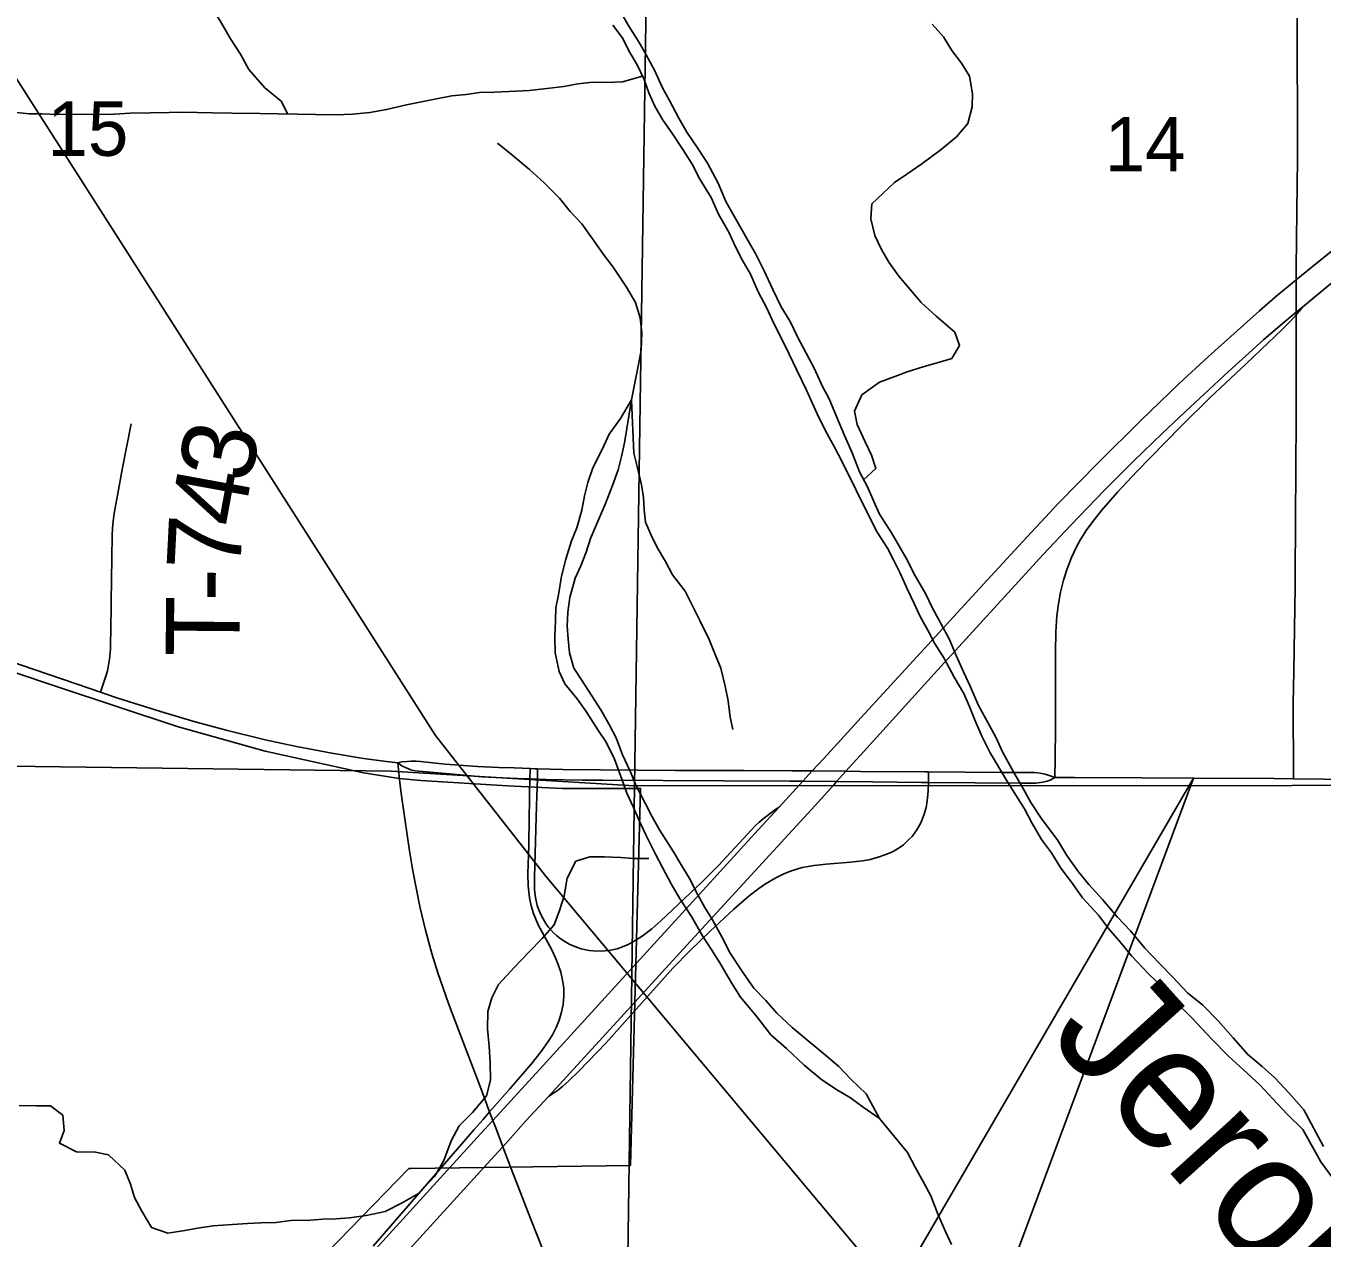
# Model space of a CAD drawing. Extents: x 0 to 34, y 0 to 22.
# Drawn here: x 16.641 to 17.64, y 16.839 to 17.772 of the extents above; entities that cross this region are included whole.
import ezdxf

# ---------------------------------------------------------------- set-up
doc = ezdxf.new("R2010")
doc.units = 0
for name, color, linetype in [('GM_X_Corporation', 7, 'Continuous'), ('GM_X_County_Road', 7, 'Continuous'), ('GM_X_Interchange_Ramps', 7, 'Continuous'), ('GM_X_Interstate_Route', 7, 'Continuous'), ('GM_X_Major_River', 7, 'Continuous'), ('GM_X_Major_River_Text', 7, 'Continuous'), ('GM_X_Minor_River', 7, 'Continuous'), ('GM_X_Rail_Line', 7, 'Continuous'), ('GM_X_Section', 7, 'Continuous'), ('GM_X_Section_Text', 7, 'Continuous'), ('GM_X_Township_Road', 7, 'Continuous'), ('GM_X_Township_Road_Text', 7, 'Continuous'), ('GM_X_US_Location', 7, 'Continuous'), ('GM_X_US_Route', 7, 'Continuous'), ('SH_Text', 7, 'Continuous')]:
    doc.layers.add(name, color=color, linetype=linetype)

msp = doc.modelspace()

# ---------------------------------------------------------------- linework, layer by layer
at = {"layer": 'GM_X_Corporation'}
msp.add_lwpolyline([(16.75517, 16.70645), (16.9364, 16.89274), (16.93792, 16.89273), (17.10691, 16.89509), (17.11474, 17.18529), (17.05464, 17.18529), (17.01229, 17.18726), (16.94547, 17.19147), (16.92893, 17.19284), (16.90141, 17.19739), (16.82566, 17.21406), (16.75792, 17.23304), (16.66586, 17.26338), (16.59752, 17.2862)], dxfattribs=at)
at = {"layer": 'GM_X_County_Road'}
msp.add_line((16.92915, 17.19217), (16.92782, 17.20492), dxfattribs=at)
for points in [[(17.01533, 16.89187), (17.00867, 16.90946), (17.00322, 16.92386), (17.00102, 16.92969), (16.99853, 16.93626), (16.99112, 16.95584), (16.97449, 16.99937), (16.96674, 17.01972), (16.95864, 17.04326), (16.95398, 17.05812), (16.94904, 17.07615), (16.94482, 17.09435), (16.93933, 17.12182), (16.93675, 17.13717), (16.93328, 17.16181), (16.93007, 17.18335), (16.92915, 17.19217)], [(17.04034, 16.8282), (17.02995, 16.85419), (17.01533, 16.89187)]]:
    msp.add_lwpolyline(points, dxfattribs=at)
at = {"layer": 'GM_X_Interchange_Ramps'}
for points in [[(17.43379, 17.19368), (17.43396, 17.20766), (17.43409, 17.21467), (17.4343, 17.22523), (17.43422, 17.29026), (17.43451, 17.30573), (17.43537, 17.31809), (17.43652, 17.32731), (17.43819, 17.33644), (17.44041, 17.34546), (17.4432, 17.35432), (17.44655, 17.36298), (17.45055, 17.37136), (17.45353, 17.37677), (17.45849, 17.38462), (17.46398, 17.39209), (17.46981, 17.39932), (17.48214, 17.41324), (17.4969, 17.42912), (17.51848, 17.45133), (17.53187, 17.46481), (17.55321, 17.48583), (17.5814, 17.51234), (17.59797, 17.52822), (17.60879, 17.53864), (17.6149, 17.54481), (17.61957, 17.54995), (17.62449, 17.55585)], [(17.02976, 17.20054), (17.02974, 17.19952), (17.02958, 17.19256), (17.02934, 17.18196), (17.02921, 17.17578), (17.02895, 17.16326), (17.02874, 17.14146), (17.02806, 17.1196), (17.02824, 17.11023), (17.02922, 17.10092), (17.03054, 17.09486), (17.03233, 17.08891), (17.03599, 17.08032), (17.04631, 17.06101), (17.04904, 17.0554), (17.05142, 17.0496), (17.05335, 17.04368), (17.05475, 17.03761), (17.05555, 17.03143), (17.05567, 17.02521), (17.05512, 17.01901), (17.05392, 17.01289), (17.05209, 17.00695), (17.04973, 17.00118), (17.04685, 16.99565), (17.04363, 16.99031), (17.03824, 16.98263), (17.03042, 16.97288), (17.01401, 16.95403), (16.99853, 16.93626), (16.99351, 16.9305), (16.98667, 16.92263), (16.9772, 16.91174), (16.90875, 16.83294)], [(17.22144, 17.17087), (17.219, 17.16926), (17.21444, 17.16607), (17.20913, 17.16192), (17.2061, 17.15936), (17.2031, 17.15641), (17.17507, 17.12615), (17.16186, 17.11308), (17.13034, 17.08326), (17.12333, 17.07714), (17.11593, 17.07151), (17.11072, 17.06816), (17.10526, 17.06519), (17.09955, 17.06278), (17.09661, 17.06185), (17.09058, 17.06049), (17.08441, 17.05996), (17.07822, 17.06017), (17.07515, 17.06056), (17.06909, 17.06189), (17.06613, 17.06283), (17.06041, 17.06523), (17.05767, 17.06667), (17.05503, 17.0683), (17.0525, 17.07009), (17.05009, 17.07204), (17.04782, 17.07414), (17.04567, 17.07638), (17.04368, 17.07875), (17.04183, 17.08124), (17.03863, 17.08655), (17.03617, 17.09221), (17.03518, 17.09515), (17.03387, 17.10118), (17.0332, 17.10732), (17.03299, 17.11663), (17.03444, 17.16312), (17.03492, 17.17966), (17.03527, 17.19239), (17.03546, 17.19947), (17.03548, 17.20036)], [(17.29344, 17.13111), (17.29777, 17.13223), (17.30365, 17.13427), (17.30931, 17.13682), (17.31465, 17.14003), (17.31715, 17.14184), (17.32172, 17.14607), (17.32381, 17.14834), (17.3275, 17.15334), (17.33054, 17.15878), (17.33292, 17.16455), (17.33467, 17.17052), (17.33532, 17.17356), (17.33608, 17.18029), (17.33629, 17.18362), (17.33639, 17.18985)], [(17.33639, 17.18985), (17.33652, 17.19698), (17.33654, 17.19812)], [(17.04382, 16.94812), (17.05068, 16.95275), (17.05456, 16.95588), (17.05939, 16.96021), (17.06741, 16.96776), (17.08801, 16.9891), (17.13962, 17.04684), (17.15264, 17.06024), (17.16833, 17.07537), (17.18666, 17.09224), (17.19844, 17.10245), (17.20583, 17.10818), (17.21093, 17.11174), (17.21896, 17.11651), (17.22455, 17.11924), (17.23029, 17.12162), (17.23921, 17.12432), (17.24836, 17.12605), (17.25765, 17.12702), (17.27632, 17.12838), (17.28561, 17.12953), (17.29171, 17.13067), (17.29344, 17.13111)]]:
    msp.add_lwpolyline(points, dxfattribs=at)
at = {"layer": 'GM_X_Interstate_Route'}
for points in [[(17.60938, 17.56843), (17.61965, 17.57682), (17.63187, 17.5868), (17.68505, 17.62973)], [(17.22144, 17.17087), (17.23972, 17.19072), (17.24703, 17.19868), (17.2558, 17.2082), (17.28722, 17.24264), (17.34186, 17.30214), (17.37545, 17.33881), (17.40908, 17.37543), (17.43667, 17.40489), (17.46704, 17.43599), (17.50015, 17.46876), (17.52932, 17.49667), (17.55206, 17.51779), (17.59133, 17.55305), (17.60542, 17.5652), (17.60938, 17.56843)], [(17.62449, 17.55585), (17.64901, 17.57602)], [(17.26373, 17.18829), (17.26573, 17.19049), (17.27291, 17.19843), (17.28668, 17.21362), (17.34098, 17.27347), (17.42481, 17.36529), (17.44605, 17.38802), (17.47201, 17.41484), (17.494, 17.43685), (17.51641, 17.45843), (17.52999, 17.47122), (17.53437, 17.47533), (17.5487, 17.48876), (17.56762, 17.5062), (17.5805, 17.51806), (17.59453, 17.53065), (17.60736, 17.54169), (17.61957, 17.5518), (17.62449, 17.55585)], [(17.11026, 17.0206), (17.14193, 17.0554), (17.18815, 17.10578), (17.24912, 17.17216), (17.26373, 17.18829)], [(16.89292, 16.81105), (16.99155, 16.91933), (17.00102, 16.92969), (17.03976, 16.97208), (17.09003, 17.02719), (17.16556, 17.1097), (17.20532, 17.15335), (17.22144, 17.17087)], [(16.99408, 16.89332), (16.99949, 16.89925), (17.00867, 16.90946), (17.0265, 16.9293), (17.04382, 16.94812), (17.10217, 17.01172), (17.11026, 17.0206)], [(16.93454, 16.82811), (16.99408, 16.89332)]]:
    msp.add_lwpolyline(points, dxfattribs=at)
at = {"layer": 'GM_X_Major_River'}
for points in [[(17.40256, 17.19694), (17.39351, 17.21333), (17.38824, 17.22475), (17.38069, 17.23884), (17.37503, 17.24913), (17.36863, 17.26397), (17.36336, 17.27502), (17.35771, 17.28758), (17.35244, 17.30053), (17.33924, 17.32452), (17.33434, 17.3348), (17.32528, 17.3508), (17.32039, 17.36071), (17.31435, 17.37099), (17.30793, 17.38204), (17.29887, 17.39652), (17.29435, 17.40604), (17.28946, 17.41746), (17.28342, 17.42889), (17.27778, 17.44373), (17.27175, 17.45706), (17.26573, 17.47153), (17.26008, 17.48523), (17.2548, 17.49476), (17.2484, 17.50884), (17.24237, 17.52027), (17.23558, 17.53284), (17.22993, 17.54465), (17.22313, 17.55608), (17.21673, 17.5694), (17.20957, 17.58426), (17.20353, 17.59644), (17.1975, 17.60673), (17.18693, 17.62578), (17.18052, 17.6372), (17.1745, 17.65129), (17.1662, 17.66653), (17.15903, 17.67758), (17.15034, 17.69054), (17.1443, 17.7012), (17.13714, 17.71492), (17.13148, 17.7252), (17.12583, 17.73777), (17.11904, 17.74996), (17.11376, 17.75948), (17.10583, 17.77205), (17.09942, 17.78348)], [(17.09331, 17.77287), (17.10049, 17.76334), (17.10652, 17.75191), (17.11218, 17.74239), (17.11746, 17.73096), (17.12121, 17.72069), (17.12573, 17.71041), (17.13177, 17.70012), (17.13932, 17.68907), (17.14726, 17.67725), (17.15443, 17.66582), (17.16046, 17.65439), (17.16914, 17.6403), (17.17479, 17.62735), (17.18309, 17.61287), (17.18761, 17.60259), (17.19289, 17.59231), (17.1993, 17.58126), (17.20533, 17.56755), (17.21212, 17.55499), (17.21739, 17.54318), (17.22456, 17.52909), (17.22908, 17.51957), (17.23511, 17.50738), (17.24264, 17.49177), (17.25168, 17.47121), (17.25847, 17.45826), (17.26413, 17.44798), (17.26978, 17.43731), (17.29165, 17.39314), (17.29692, 17.38247), (17.30485, 17.37028), (17.30975, 17.36076), (17.31465, 17.35085), (17.3203, 17.33829), (17.32558, 17.32762), (17.3301, 17.31772), (17.33614, 17.30668), (17.34104, 17.29716), (17.34821, 17.28572), (17.35613, 17.27087), (17.36368, 17.2583), (17.36782, 17.24878), (17.37196, 17.2385), (17.37761, 17.22555), (17.38401, 17.21261)], [(17.38401, 17.21261), (17.39647, 17.19165), (17.40251, 17.18213), (17.41044, 17.16955), (17.41609, 17.15889), (17.42364, 17.14593), (17.4312, 17.13564), (17.43837, 17.12383), (17.44744, 17.11201), (17.45499, 17.10095), (17.46747, 17.0876), (17.47503, 17.0773), (17.48486, 17.06624), (17.4928, 17.05633), (17.50603, 17.04259), (17.51739, 17.03152), (17.5257, 17.02198), (17.53932, 17.00862), (17.55445, 16.99259), (17.56769, 16.97885), (17.57904, 16.96855), (17.59153, 16.95709), (17.60174, 16.9464), (17.61271, 16.93458), (17.62482, 16.92274)], [(17.62563, 16.93794), (17.61391, 16.95091), (17.60332, 16.96236), (17.59348, 16.97114), (17.5825, 16.98031), (17.57116, 16.99328), (17.55944, 17.00625), (17.54771, 17.01846), (17.53598, 17.02801), (17.52463, 17.03984), (17.51442, 17.05053), (17.50307, 17.06236), (17.49211, 17.07571), (17.48189, 17.08639), (17.47055, 17.09974), (17.45996, 17.11119), (17.45203, 17.12111), (17.44296, 17.13369), (17.43617, 17.14512), (17.42332, 17.16227), (17.41539, 17.17447), (17.40822, 17.18742), (17.40256, 17.19694)], [(17.64056, 16.90963), (17.62563, 16.93794)], [(17.62482, 16.92274), (17.6386, 16.89787), (17.64701, 16.88629)]]:
    msp.add_lwpolyline(points, dxfattribs=at)
at = {"layer": 'GM_X_Minor_River'}
for points in [[(16.84324, 17.70445), (16.83796, 17.71435), (16.82547, 17.72467), (16.81299, 17.73878), (16.80658, 17.75059), (16.79903, 17.7624), (16.79111, 17.77612), (16.78242, 17.78946), (16.77222, 17.80242), (16.76543, 17.81386), (16.75563, 17.83442), (16.75035, 17.84546), (16.74621, 17.85498)], [(17.28656, 17.42294), (17.29596, 17.43149), (17.29258, 17.44177), (17.28768, 17.45205), (17.28165, 17.46538), (17.27941, 17.47565), (17.28515, 17.48816), (17.29885, 17.49798), (17.31064, 17.50249), (17.32014, 17.50586), (17.33307, 17.50999), (17.34485, 17.51335), (17.35435, 17.51635), (17.36046, 17.5262), (17.3567, 17.53648), (17.34232, 17.5487), (17.33097, 17.55939), (17.32227, 17.56931), (17.31357, 17.57961), (17.30602, 17.59028), (17.30036, 17.60019), (17.29508, 17.61085), (17.29209, 17.62379), (17.29289, 17.63518), (17.31042, 17.65182), (17.31993, 17.65824), (17.33135, 17.66617), (17.3462, 17.67712), (17.358, 17.68695), (17.36677, 17.69717), (17.37023, 17.71008), (17.37027, 17.71995), (17.36804, 17.73364), (17.362, 17.74355), (17.35444, 17.75346), (17.34803, 17.76375), (17.33933, 17.77367)], [(17.11622, 17.73363), (17.10074, 17.72914), (17.08897, 17.72881), (17.07796, 17.72886), (17.06657, 17.72777), (17.05555, 17.72554), (17.04264, 17.72408), (17.02896, 17.72262), (17.01871, 17.72191), (17.00238, 17.72122), (16.99061, 17.72089), (16.98036, 17.71942), (16.96934, 17.71833), (16.95756, 17.7161), (16.94617, 17.71387), (16.93439, 17.71164), (16.91919, 17.70791), (16.90627, 17.70569), (16.89298, 17.70423), (16.88045, 17.7039), (16.8645, 17.70397), (16.85046, 17.70442), (16.83565, 17.70448), (16.8216, 17.70493), (16.79996, 17.70502), (16.78516, 17.70547), (16.77339, 17.70552), (16.76276, 17.70595), (16.75175, 17.70562), (16.73732, 17.7053), (16.72175, 17.70499), (16.7096, 17.70429), (16.69555, 17.70397), (16.68379, 17.7044), (16.66594, 17.7041), (16.65379, 17.70454), (16.64392, 17.70458), (16.63216, 17.70577)], [(17.10784, 17.48439), (17.11093, 17.49996), (17.11325, 17.51173), (17.11519, 17.52274), (17.11562, 17.53604), (17.11452, 17.54744), (17.11076, 17.55924), (17.10397, 17.57105), (17.09378, 17.58667), (17.08622, 17.59621), (17.07904, 17.6065), (17.0696, 17.61984), (17.06052, 17.62938), (17.05221, 17.63968), (17.04048, 17.65151), (17.02912, 17.66182), (17.01663, 17.67214), (17.00452, 17.68207)], [(17.10784, 17.48439), (17.09943, 17.46999), (17.09066, 17.45787), (17.0853, 17.44612), (17.07804, 17.43209), (17.0742, 17.42071), (17.07151, 17.41046), (17.06957, 17.39945), (17.06572, 17.38579), (17.06151, 17.37592), (17.05728, 17.36188), (17.05382, 17.3486), (17.05149, 17.33417), (17.04956, 17.3243), (17.04914, 17.31442), (17.04872, 17.30188), (17.04905, 17.28972), (17.05204, 17.27527), (17.05656, 17.26575), (17.06601, 17.25431), (17.07281, 17.2444), (17.08187, 17.2303), (17.08829, 17.22077), (17.0947, 17.20782), (17.09921, 17.19526), (17.1041, 17.18156), (17.10937, 17.17052), (17.11351, 17.161), (17.11879, 17.14958), (17.12633, 17.13472), (17.13161, 17.12444), (17.13839, 17.11187), (17.14481, 17.10082), (17.15387, 17.08672), (17.16255, 17.07186), (17.16972, 17.06081), (17.17576, 17.0509), (17.18482, 17.03566), (17.19161, 17.02462), (17.20371, 17.01012), (17.21505, 16.99563), (17.22716, 16.98494), (17.24078, 16.97234), (17.25441, 16.96088), (17.26653, 16.95284), (17.27638, 16.9471), (17.28622, 16.93983), (17.29872, 16.93104)], [(17.10784, 17.48439), (17.1024, 17.45136), (17.10009, 17.44073), (17.09739, 17.43048), (17.09318, 17.41834), (17.08781, 17.40469), (17.08168, 17.39027), (17.07632, 17.37776), (17.07287, 17.36713), (17.06865, 17.35651), (17.06444, 17.34703), (17.06021, 17.33223), (17.05866, 17.32084), (17.05824, 17.3102), (17.05896, 17.30032), (17.06006, 17.28967), (17.06344, 17.27788), (17.06986, 17.26797), (17.07665, 17.2573), (17.08421, 17.24587), (17.09062, 17.23444), (17.0959, 17.22415), (17.10078, 17.21121), (17.10682, 17.19865), (17.11133, 17.18723), (17.1185, 17.17352), (17.12339, 17.16399), (17.12943, 17.15333), (17.14, 17.13656), (17.14566, 17.12704), (17.15246, 17.11599), (17.15887, 17.10342), (17.16415, 17.09351), (17.17018, 17.08399), (17.17735, 17.07104), (17.18376, 17.05847), (17.1932, 17.04399), (17.20189, 17.03141), (17.21135, 17.02187), (17.21967, 17.01233), (17.23139, 17.00126), (17.24389, 16.99094), (17.25714, 16.97986), (17.26735, 16.97108), (17.27681, 16.96154), (17.28854, 16.95008), (17.29872, 16.93104)], [(17.10784, 17.48439), (17.10959, 17.44335), (17.11221, 17.43308), (17.11558, 17.419), (17.11706, 17.40911), (17.11741, 17.39961), (17.11851, 17.39011), (17.12303, 17.38021), (17.12755, 17.37069), (17.13397, 17.36002), (17.13925, 17.34974), (17.14907, 17.33715), (17.15435, 17.32687), (17.16076, 17.31392), (17.16754, 17.29983), (17.17168, 17.28955), (17.17658, 17.27775), (17.17994, 17.26406), (17.18218, 17.25265), (17.18365, 17.2401), (17.1859, 17.23059)], [(16.63633, 16.94106), (16.64963, 16.94101), (16.66027, 16.94097), (16.66974, 16.93372), (16.67085, 16.92193), (16.6674, 16.91206), (16.6803, 16.90556), (16.69511, 16.90513), (16.70498, 16.90319), (16.71749, 16.89137), (16.72201, 16.88071), (16.72502, 16.87044), (16.73069, 16.85978), (16.73825, 16.84721), (16.75078, 16.84299), (16.7637, 16.84484), (16.77358, 16.84671), (16.78574, 16.84856), (16.80056, 16.84965), (16.81196, 16.85037), (16.82221, 16.85072), (16.83399, 16.85105), (16.84539, 16.85254), (16.86059, 16.85286), (16.87009, 16.85359), (16.87996, 16.85393), (16.8906, 16.85466), (16.90353, 16.85651), (16.91797, 16.8595), (16.93128, 16.8663), (16.94384, 16.87347), (16.95642, 16.88673), (16.96329, 16.89886), (16.96903, 16.91405), (16.97514, 16.92542), (16.98543, 16.93565), (16.9961, 16.94853), (16.99918, 16.96068), (16.99883, 16.97398), (16.99811, 16.98691), (16.99701, 17.00021), (16.99705, 17.01351), (17.00012, 17.02415), (17.00546, 17.03439), (17.01766, 17.04765), (17.02909, 17.05939), (17.039, 17.06961), (17.04814, 17.08022), (17.05235, 17.09122), (17.05581, 17.10261), (17.05812, 17.11629), (17.065, 17.12919), (17.07565, 17.13257), (17.08704, 17.13253), (17.09958, 17.1321), (17.10907, 17.13131), (17.12123, 17.13127)], [(17.29872, 16.93104), (17.32027, 16.9051), (17.3263, 16.89368), (17.33271, 16.88225), (17.33837, 16.87158), (17.34402, 16.85712), (17.34928, 16.84456), (17.35418, 16.83427)]]:
    msp.add_lwpolyline(points, dxfattribs=at)
at = {"layer": 'GM_X_Rail_Line'}
msp.add_lwpolyline([(17.91677, 16.34), (17.62614, 16.49085), (17.58753, 16.51429), (17.54723, 16.53981), (17.50751, 16.57084), (17.47262, 16.60675), (17.41087, 16.67499), (17.34012, 16.75867), (17.28737, 16.82433), (17.04167, 17.11786), (16.95677, 17.22601), (16.87058, 17.36118), (16.63389, 17.73196), (16.39363, 18.10985), (16.36893, 18.14437), (16.34317, 18.17612), (16.30708, 18.2084), (16.27461, 18.2294), (16.21709, 18.26238), (16.14636, 18.29525), (15.65156, 18.4846)], dxfattribs=at)
at = {"layer": 'GM_X_Section'}
for points in [[(17.12534, 18.20792), (17.11005, 17.18727), (16.92281, 17.19862), (16.09999, 17.2094), (16.11682, 18.21604)], [(17.12534, 18.20792), (18.12874, 18.1928), (18.12281, 17.18769), (17.11005, 17.18727)], [(16.09999, 17.2094), (16.92281, 17.19862), (17.11005, 17.18727), (17.09585, 16.18898), (16.08772, 16.1952)], [(18.12281, 17.18769), (18.11686, 16.1822), (17.09585, 16.18898), (17.11005, 17.18727)]]:
    msp.add_lwpolyline(points, close=True, dxfattribs=at)
at = {"layer": 'GM_X_Township_Road'}
for points in [[(17.61764, 17.19263), (17.61754, 17.21751), (17.61727, 17.22894), (17.61736, 17.25066), (17.61778, 17.27548), (17.61877, 17.34067), (17.61913, 17.39967), (17.61937, 17.42449), (17.61956, 17.47723), (17.61958, 17.52998), (17.61957, 17.54995), (17.61957, 17.5518), (17.61957, 17.55792), (17.61965, 17.57682), (17.61969, 17.58586), (17.62022, 17.62931), (17.62068, 17.66966), (17.62058, 17.71312), (17.62047, 17.74106), (17.62047, 17.7783)], [(16.69886, 17.25926), (16.70265, 17.27079), (16.70421, 17.27582), (16.70512, 17.28011), (16.70586, 17.28489), (16.70652, 17.2925), (16.70663, 17.29879), (16.70672, 17.30526), (16.70717, 17.32854), (16.70744, 17.34643), (16.70762, 17.36235), (16.7079, 17.38024), (16.70798, 17.38545), (16.70852, 17.39094), (16.70907, 17.39507), (16.70979, 17.39993), (16.71212, 17.41219), (16.71566, 17.4307), (16.71888, 17.44759), (16.72237, 17.46591)]]:
    msp.add_lwpolyline(points, dxfattribs=at)
at = {"layer": 'GM_X_US_Route'}
for points in [[(16.26836, 17.41004), (16.38063, 17.36959), (16.41632, 17.35658), (16.42569, 17.35329), (16.46664, 17.33891), (16.53416, 17.31521), (16.55077, 17.30937), (16.56256, 17.30521), (16.5863, 17.29736), (16.60076, 17.29259), (16.61582, 17.2876), (16.69059, 17.26208), (16.69886, 17.25926), (16.70987, 17.25549), (16.71213, 17.25478), (16.74519, 17.24436), (16.77182, 17.23649), (16.79565, 17.23003), (16.82565, 17.22276), (16.84979, 17.21758), (16.87706, 17.21237), (16.90142, 17.20833), (16.91717, 17.20617), (16.92782, 17.20492)], [(16.92782, 17.20492), (16.93091, 17.20562), (16.9349, 17.20604), (16.93812, 17.20618), (16.94183, 17.20625), (16.9454, 17.20603), (16.96437, 17.20405), (16.98911, 17.20203), (17.00573, 17.20139), (17.01741, 17.20099), (17.02976, 17.20054), (17.03333, 17.20041), (17.03548, 17.20036), (17.05502, 17.19991), (17.14168, 17.1991), (17.19431, 17.19908), (17.23144, 17.19883), (17.24703, 17.19868), (17.27291, 17.19843), (17.28407, 17.19832), (17.33361, 17.19816), (17.33654, 17.19812), (17.39241, 17.19755), (17.41821, 17.19752), (17.42239, 17.19702), (17.42635, 17.19619), (17.43031, 17.195), (17.43379, 17.19368)], [(16.92782, 17.20492), (16.93098, 17.20275), (16.93413, 17.20107), (16.93791, 17.1996), (16.94113, 17.19883), (16.94393, 17.19857), (16.96467, 17.19674), (16.99251, 17.1943), (17.01418, 17.19304), (17.02657, 17.19265), (17.02958, 17.19256), (17.03527, 17.19239), (17.04206, 17.19218), (17.06997, 17.19172), (17.07926, 17.19167), (17.08546, 17.19165), (17.1786, 17.19109), (17.22962, 17.19079)], [(17.22962, 17.19079), (17.23762, 17.19074), (17.23972, 17.19072), (17.26573, 17.19049), (17.29354, 17.19025), (17.3308, 17.18989), (17.33639, 17.18985), (17.40844, 17.18943), (17.41925, 17.18931), (17.42447, 17.19007), (17.42788, 17.19076), (17.43073, 17.19187), (17.43379, 17.19368)], [(17.43379, 17.19368), (17.44882, 17.19364), (17.5004, 17.1934), (17.54068, 17.19318)], [(17.54068, 17.19318), (17.60272, 17.19292), (17.61764, 17.19263)], [(17.61764, 17.19263), (17.73418, 17.19142), (17.75903, 17.19102), (17.83367, 17.19076), (17.89276, 17.19031), (17.93006, 17.18989), (17.98915, 17.18979), (18.06068, 17.18952), (18.09798, 17.18909), (18.12527, 17.18911), (18.15084, 17.18914), (18.17573, 17.18907), (18.23791, 17.1888), (18.29388, 17.18885), (18.36541, 17.18895), (18.3754, 17.18888)]]:
    msp.add_lwpolyline(points, dxfattribs=at)
at = {"layer": 'SH_Text'}
msp.add_lwpolyline([(16.65699, 15.67538), (17.54068, 17.19318), (16.97557, 15.67538)], close=True, dxfattribs=at)

# ---------------------------------------------------------------- texts
at = {"layer": 'GM_X_Major_River_Text'}
msp.add_text('Jerome Fork', height=0.0947295, rotation=311.99149, dxfattribs=at).set_placement((17.42743, 16.99451))
at = {"layer": 'GM_X_Section_Text'}
for s, p in [('15', (16.65803, 17.67225)), ('14', (17.4722, 17.66038))]:
    msp.add_text(s, height=0.041856, rotation=0.00001, dxfattribs=at).set_placement(p)
at = {"layer": 'GM_X_Township_Road_Text'}
for s, rotation, p in [('3', 79.56575, (16.81425, 17.41925)), ('4', 79.63417, (16.80795, 17.38484)), ('7', 87.07418, (16.80639, 17.35182)), ('-', 89.47701, (16.8062, 17.32912)), ('T', 89.48572, (16.80582, 17.28662))]:
    msp.add_text(s, height=0.05682, rotation=rotation, dxfattribs=at).set_placement(p)
at = {"layer": 'GM_X_US_Location'}
for s, p in [('0', (16.99046, 17.19533)), ('/', (16.99048, 17.19533))]:
    msp.add_text(s, height=0.000189, dxfattribs=at).set_placement(p)
msp.add_text('250', height=0.000189, rotation=0.00001, dxfattribs=at).set_placement((16.9322, 17.15612))

doc.saveas('drawing.dxf')
